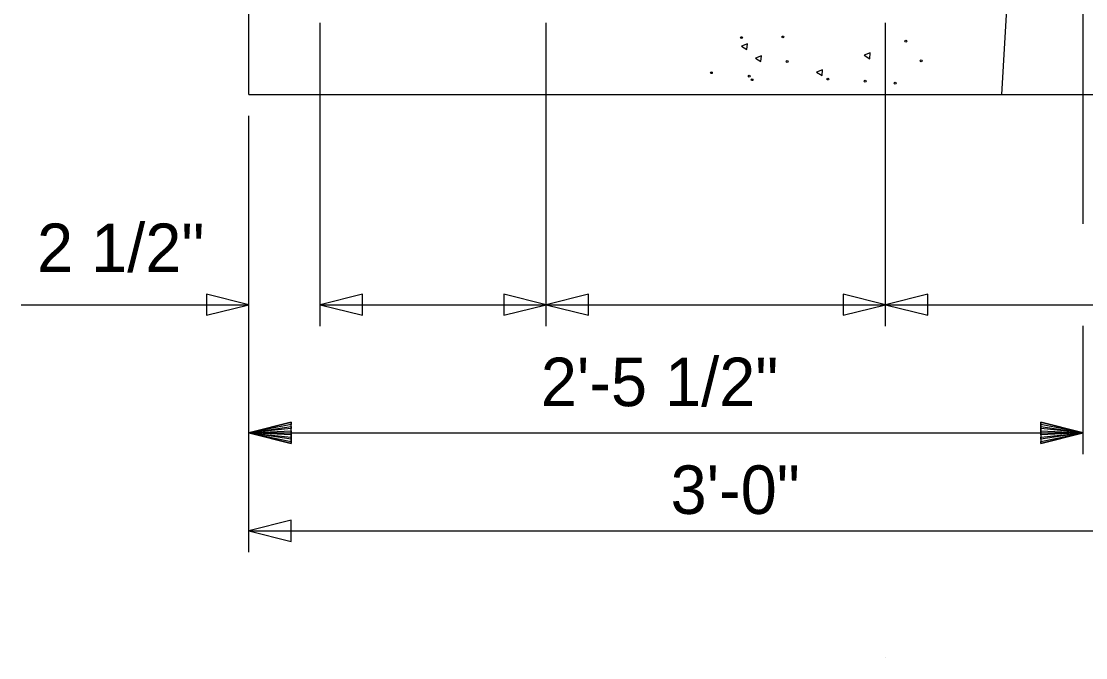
# Model space of a CAD drawing. Extents: x 0 to 177, y -1 to 127.
# Drawn here: x 145.428 to 148.564, y 88.851 to 90.728 of the extents above; entities that cross this region are included whole.
import ezdxf

# ---------------------------------------------------------------- set-up
doc = ezdxf.new("R2010")
doc.units = 0
for name, color, linetype in [('Arrowhead Terminators CELL', 7, 'Continuous'), ('Dimension Lines', 7, 'Continuous'), ('Mis Center Lines', 7, 'Continuous'), ('Sup Concrete Girder Lines', 7, 'Continuous'), ('Text', 7, 'Continuous'), ('User Information Notes', 7, 'Continuous')]:
    doc.layers.add(name, color=color, linetype=linetype)

msp = doc.modelspace()

# ---------------------------------------------------------------- linework, layer by layer
at = {"layer": 'Arrowhead Terminators CELL'}
for points in [[(146.0981, 89.8921), (145.9731, 89.9234), (145.9731, 89.8609)], [(146.3079, 89.8921), (146.4329, 89.8609), (146.4329, 89.9234)], [(146.9742, 89.8921), (146.8492, 89.9234), (146.8492, 89.8609)], [(146.9742, 89.8921), (147.0992, 89.8609), (147.0992, 89.9234)], [(147.9742, 89.8921), (147.8492, 89.9234), (147.8492, 89.8609)], [(147.9742, 89.8921), (148.0992, 89.8609), (148.0992, 89.9234)], [(146.0981, 89.2255), (146.2231, 89.1942), (146.2231, 89.2567)]]:
    msp.add_lwpolyline(points, close=True, dxfattribs=at)
at = {"layer": 'Dimension Lines'}
for p, q in [((146.3079, 89.8291), (146.3079, 90.7228)), ((146.9742, 89.8291), (146.9742, 90.7228)), ((147.9742, 89.8291), (147.9742, 90.7228)), ((148.5564, 90.1304), (148.5564, 90.7031)), ((146.0981, 89.1624), (146.0981, 90.4488)), ((145.4276, 89.8921), (146.0981, 89.8921)), ((146.3079, 89.8921), (146.9742, 89.8921)), ((146.9742, 89.8921), (147.9742, 89.8921)), ((147.9742, 89.8921), (148.9742, 89.8921)), ((148.5564, 89.4512), (148.5564, 89.8296)), ((146.0981, 89.5142), (148.5564, 89.5142)), ((146.0981, 89.2255), (149.0981, 89.2255))]:
    msp.add_line(p, q, dxfattribs=at)
for points in [[(146.2231, 89.5142), (146.2231, 89.508), (146.0981, 89.5142), (146.2231, 89.5017), (146.2231, 89.4955), (146.0981, 89.5142), (146.2231, 89.4892), (146.2231, 89.483), (146.0981, 89.5142), (146.2231, 89.5455), (146.2231, 89.5392), (146.0981, 89.5142), (146.2231, 89.533), (146.2231, 89.5267), (146.0981, 89.5142), (146.2231, 89.5205), (146.2231, 89.483), (146.2231, 89.5455), (146.0981, 89.5142), (146.2231, 89.483)], [(148.4314, 89.5142), (148.4314, 89.5205), (148.5564, 89.5142), (148.4314, 89.5267), (148.4314, 89.533), (148.5564, 89.5142), (148.4314, 89.5392), (148.4314, 89.5455), (148.5564, 89.5142), (148.4314, 89.483), (148.4314, 89.4892), (148.5564, 89.5142), (148.4314, 89.4955), (148.4314, 89.5017), (148.5564, 89.5142), (148.4314, 89.508), (148.4314, 89.5455), (148.4314, 89.483), (148.5564, 89.5142), (148.4314, 89.5455)]]:
    msp.add_lwpolyline(points, dxfattribs=at)
at = {"layer": 'Mis Center Lines'}
msp.add_line((148.5564, 90.5113), (148.5564, 93.5113), dxfattribs=at)
at = {"layer": 'Sup Concrete Girder Lines'}
for q in [(146.0981, 93.5113), (149.8415, 90.5113)]:
    msp.add_line((146.0981, 90.5113), q, dxfattribs=at)
for points in [[(148.3168, 90.5113), (148.3377, 90.8655), (148.7752, 90.8655), (148.796, 90.5113)], [(147.5658, 90.6442), (147.5674, 90.6614), (147.5494, 90.6543), (147.5658, 90.6442)], [(147.6072, 90.6091), (147.6087, 90.6262), (147.5907, 90.6192), (147.6072, 90.6091)], [(147.9278, 90.6173), (147.9293, 90.6345), (147.9113, 90.6274), (147.9278, 90.6173)], [(147.7871, 90.5677), (147.7887, 90.5848), (147.7707, 90.5778), (147.7871, 90.5677)]]:
    msp.add_lwpolyline(points, dxfattribs=at)
for centre in [(147.55, 90.6795), (147.6719, 90.6815), (148.0339, 90.6691), (147.6843, 90.6092), (148.0793, 90.6112), (147.461, 90.576), (147.5727, 90.5657), (147.5809, 90.5554), (147.8043, 90.5574), (147.9139, 90.5512), (148.0028, 90.5451)]:
    msp.add_circle(centre, 0.00273, dxfattribs=at)
at = {"layer": 'User Information Notes'}
msp.add_line((147.9731, 88.8512), (147.9731, 88.8512), dxfattribs=at)

# ---------------------------------------------------------------- texts
at = {"layer": 'Text'}
for s, p in [('2 1/2"', (145.474, 89.9883)), ('2\'-5 1/2"', (146.9585, 89.5929)), ('3\'-0"', (147.3408, 89.2752))]:
    msp.add_text(s, height=0.14302, dxfattribs=at).set_placement(p)

doc.saveas('drawing.dxf')
